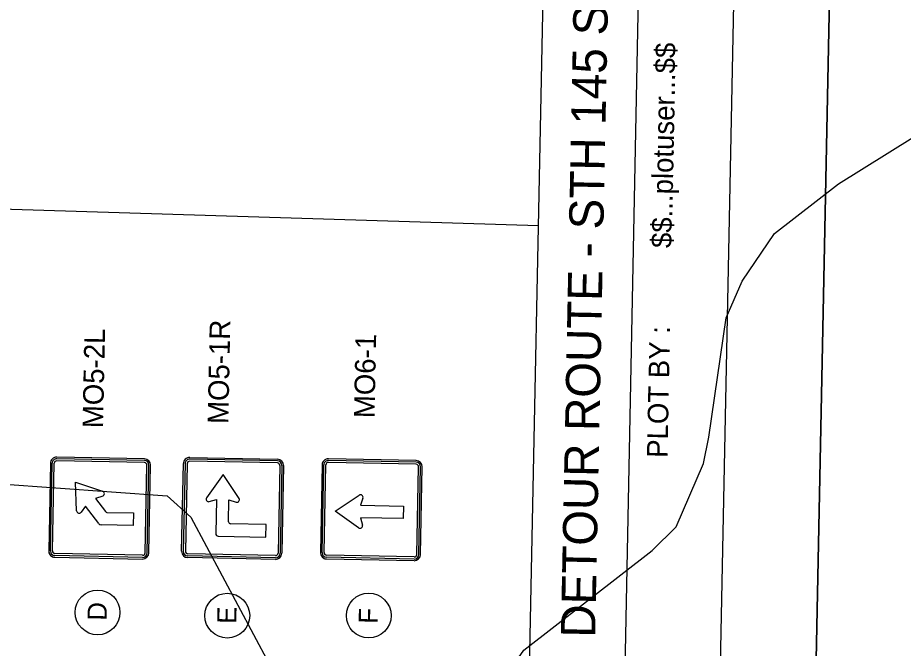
# Model space of a CAD drawing. Extents: x 331323 to 388339, y 121519 to 205315.
# Drawn here: x 365701 to 368485, y 141380 to 143362 of the extents above; entities that cross this region are included whole.
import ezdxf

# ---------------------------------------------------------------- set-up
doc = ezdxf.new("R2010")
doc.units = 0
for name, color, linetype in [('CA-TEXT', 7, 'Continuous'), ('Level 4', 7, 'Continuous'), ('Level 57', 7, 'Continuous'), ('P_RDWY_Text', 7, 'Continuous'), ('P_SGN_Cell', 7, 'Continuous'), ('PLT_Sheet_Border', 7, 'Continuous'), ('PLT_Sheet_Info', 7, 'Continuous')]:
    doc.layers.add(name, color=color, linetype=linetype)

msp = doc.modelspace()

# ---------------------------------------------------------------- linework, layer by layer
at = {"layer": 'CA-TEXT'}
for centre in [(365952.4, 141492.8), (366360.2, 141482.7), (366804.9, 141482.9)]:
    msp.add_circle(centre, 70.4, dxfattribs=at)
at = {"layer": 'Level 4'}
msp.add_lwpolyline([(367338.6, 142707.9), (362672.8, 142853), (355637.9, 142792.5)], dxfattribs=at)
at = {"layer": 'Level 57'}
for points in [[(367014.6, 141051.6), (367166.1, 141191.9), (367292.8, 141374.1), (367696, 141687.1), (367771.8, 141761.4), (367857, 141960.7), (367874.5, 142043.8), (367928, 142418.4), (367979.1, 142534.6), (368080.5, 142683.7), (368282.1, 142840.2), (368676.4, 143086.6), (369005.2, 143475.3), (369619.6, 144078.1), (370015, 144449.5), (370611, 144869.2), (370778.7, 144967.6), (370812.1, 144967.3)], [(364906.3, 142137.4), (365005.8, 142069.8), (365546.9, 141964.9), (365646.4, 141897.3), (366171.4, 141859.3), (366245.9, 141791.9), (366491.8, 141331.3), (366656.8, 141138.2), (366848, 141069.8), (367014.6, 141051.6)]]:
    msp.add_lwpolyline(points, dxfattribs=at)
at = {"layer": 'P_RDWY_Text'}
msp.add_lwpolyline([(354790.8, 130527.7), (355201.6, 150923.5), (368398.9, 150657.7), (367988.1, 130261.9)], close=True, dxfattribs=at)
at = {"layer": 'P_SGN_Cell'}
for p, q in [((366099.9, 141970.3), (365824.3, 141975.8)), ((366100, 141975.5), (365824.4, 141981.1)), ((366517.7, 141969.1), (366242.2, 141974.7)), ((366242.3, 141979.9), (366517.8, 141974.4)), ((366954, 141970.4), (366678.4, 141975.9)), ((365804.4, 141961.8), (365798.8, 141686.2)), ((365804.1, 141686.1), (365809.6, 141961.7)), ((365810.6, 141686), (365816.2, 141961.5)), ((366099.8, 141963.7), (365824.2, 141969.3)), ((366101.9, 141680.1), (366107.5, 141955.7)), ((366108.5, 141680), (366114, 141955.5)), ((366113.7, 141679.9), (366119.3, 141955.4)), ((366216.6, 141685.1), (366222.2, 141960.6)), ((366227.4, 141960.5), (366221.9, 141685)), ((366234, 141960.4), (366228.5, 141684.8)), ((366517.6, 141962.6), (366242, 141968.1)), ((366525.3, 141954.5), (366519.8, 141679)), ((366531.9, 141954.4), (366526.3, 141678.8)), ((366537.1, 141954.3), (366531.6, 141678.7)), ((366658.4, 141956.6), (366652.8, 141681.1)), ((366658.1, 141681), (366663.6, 141956.5)), ((366664.6, 141680.8), (366670.2, 141956.4)), ((366953.8, 141958.6), (366678.2, 141964.1)), ((366953.9, 141965.1), (366678.3, 141970.7)), ((366955.9, 141675), (366961.5, 141950.5)), ((366962.5, 141674.8), (366968, 141950.4)), ((366967.7, 141674.7), (366973.3, 141950.3)), ((366347.5, 141926.6), (366294.9, 141853.4)), ((366397.1, 141851.3), (366347.5, 141926.6)), ((365886.6, 141812.3), (365883, 141902.4)), ((365883, 141902.4), (365968.4, 141873.6)), ((365968.6, 141858.7), (365946.4, 141850.6)), ((365946.4, 141850.6), (365977, 141809.8)), ((366303.5, 141841.2), (366326.3, 141847.6)), ((366326.3, 141847.6), (366324.1, 141740.7)), ((366364.2, 141777.9), (366365.6, 141846.8)), ((366365.6, 141846.8), (366388.1, 141839.5)), ((366699.6, 141811.6), (366774.9, 141861.2)), ((366786.8, 141852.2), (366779.5, 141829.6)), ((365914.9, 141827), (365900.8, 141807.9)), ((365956.2, 141771.8), (365914.9, 141827)), ((365982.1, 141807.2), (366065.1, 141805.5)), ((366772.9, 141759), (366699.6, 141811.6)), ((366779.5, 141829.6), (366913.9, 141826.9)), ((366913.9, 141826.9), (366913.1, 141787.6)), ((366065.1, 141805.5), (366064.3, 141766.1)), ((366913.1, 141787.6), (366778.7, 141790.3)), ((366778.7, 141790.3), (366785.1, 141767.5)), ((366064.3, 141766.1), (365963.4, 141768.2)), ((366482.2, 141769), (366370.7, 141771.2)), ((366481.4, 141729.6), (366482.2, 141769)), ((366331.8, 141732.6), (366481.4, 141729.6)), ((366093.8, 141665.8), (365818.2, 141671.4)), ((366093.9, 141672.4), (365818.3, 141677.9)), ((366511.6, 141664.7), (366236, 141670.2)), ((366511.7, 141671.2), (366236.2, 141676.8)), ((366947.9, 141667.3), (366672.3, 141672.8)), ((365818.1, 141666.1), (366093.7, 141660.6)), ((366511.5, 141659.4), (366235.9, 141665)), ((366672.1, 141661), (366947.7, 141655.5)), ((366947.8, 141660.7), (366672.2, 141666.2))]:
    msp.add_line(p, q, dxfattribs=at)
for centre, radius, start, end in [((365824, 141961.4), 19.7, 88.8462, 178.8462), ((365824, 141961.4), 14.4, 88.8462, 178.8462), ((366099.6, 141955.8), 19.7, 358.8462, 88.8462), ((366241.9, 141960.2), 19.7, 88.8462, 178.8462), ((366241.9, 141960.2), 14.4, 88.8462, 178.8462), ((366517.5, 141954.7), 19.7, 358.8462, 88.8462), ((366678, 141956.3), 19.7, 88.8468, 178.8468), ((365824, 141961.4), 7.88, 88.8462, 178.8462), ((366099.6, 141955.8), 7.88, 358.8462, 88.8462), ((366099.6, 141955.8), 14.4, 358.8462, 88.8462), ((366241.9, 141960.2), 7.88, 88.8462, 178.8462), ((366517.5, 141954.7), 7.88, 358.8462, 88.8462), ((366517.5, 141954.7), 14.4, 358.8462, 88.8462), ((366678, 141956.3), 14.4, 88.8468, 178.8468), ((366678, 141956.3), 7.87, 88.8468, 178.8468), ((366953.6, 141950.7), 7.87, 358.8468, 88.8468), ((366953.6, 141950.7), 14.4, 358.8468, 88.8468), ((366953.6, 141950.7), 19.7, 358.8468, 88.8468), ((365965.9, 141866.1), 7.87, 290.0436, 71.3759), ((366779.3, 141854.6), 7.87, 342.043, 123.3753), ((366301.3, 141848.8), 7.87, 144.3166, 285.6488), ((366390.6, 141847), 7.87, 252.0436, 33.3759), ((365894.5, 141812.6), 7.87, 182.3166, 323.6488), ((365982.2, 141813.7), 6.56, 216.8461, 268.8462), ((365963.6, 141777.3), 9.19, 216.8459, 268.8462), ((366370.8, 141777.8), 6.56, 178.8462, 268.8462), ((366777.5, 141765.4), 7.87, 234.316, 15.6482), ((366332, 141740.5), 7.88, 178.8462, 268.8462), ((365818.5, 141685.8), 19.7, 178.8462, 268.8462), ((365818.5, 141685.8), 19.7, 178.8462, 213.1868), ((365818.5, 141685.8), 14.4, 178.8462, 268.8462), ((365818.5, 141685.8), 19.7, 244.1347, 268.8462), ((365818.5, 141685.8), 7.88, 178.8462, 268.8462), ((366094.1, 141680.3), 19.7, 268.8462, 358.8462), ((366094.1, 141680.3), 14.4, 268.8462, 358.8462), ((366094.1, 141680.3), 7.88, 268.8462, 358.8462), ((366236.3, 141684.7), 19.7, 178.8462, 268.8462), ((366236.3, 141684.7), 14.4, 178.8462, 268.8462), ((366236.3, 141684.7), 7.88, 178.8462, 268.8462), ((366511.9, 141679.1), 19.7, 268.8462, 358.8462), ((366511.9, 141679.1), 14.4, 268.8462, 358.8462), ((366511.9, 141679.1), 7.88, 268.8462, 358.8462), ((366672.5, 141680.7), 19.7, 178.8468, 268.8468), ((366672.5, 141680.7), 14.4, 178.8468, 268.8468), ((366672.5, 141680.7), 7.87, 178.8468, 268.8468), ((366948.1, 141675.1), 19.7, 268.8468, 358.8468), ((366948.1, 141675.1), 14.4, 268.8468, 358.8468), ((366948.1, 141675.1), 7.87, 268.8468, 358.8468), ((366672.5, 141680.7), 19.7, 239.4503, 268.8468)]:
    msp.add_arc(centre, radius, start, end, dxfattribs=at)
at = {"layer": 'PLT_Sheet_Border'}
for points in [[(367988.1, 130261.9), (368398.9, 150657.7), (355201.6, 150923.5), (354790.8, 130527.7)], [(367691.1, 130411.9), (368091, 150267.9), (355493.5, 150521.6), (355093.6, 130665.6)]]:
    msp.add_lwpolyline(points, close=True, dxfattribs=at)
at = {"layer": 'PLT_Sheet_Info'}
for p, q in [((367103.6, 131038.8), (367484.2, 149935)), ((367403.5, 131032.8), (367784.1, 149929))]:
    msp.add_line(p, q, dxfattribs=at)

# ---------------------------------------------------------------- texts
at = {"layer": 'CA-TEXT'}
for s, p in [('D', (365980.7, 141466.7)), ('E', (366388.4, 141456.6)), ('F', (366833.1, 141456.8))]:
    msp.add_text(s, height=60, rotation=88.8468, dxfattribs=at).set_placement(p)
at = {"layer": 'P_SGN_Cell'}
for s, rotation, p in [('MO5-1R', 88.8462, (366363.4, 142084.8)), ('MO5-2L', 88.8462, (365969.8, 142071.5)), ('MO6-1', 88.8468, (366823.1, 142103))]:
    msp.add_text(s, height=64.8, rotation=rotation, dxfattribs=at).set_placement(p)
at = {"layer": 'PLT_Sheet_Info'}
for s, height, p in [('DETOUR ROUTE - STH 145 SB OFF RAMP                   ', 108, (367516.6, 141412.6)), ('$$...plotuser...$$', 64.8, (367757.3, 142638)), ('PLOT BY :', 64.8, (367744, 141978.2))]:
    msp.add_text(s, height=height, rotation=88.8462, dxfattribs=at).set_placement(p)

doc.saveas('drawing.dxf')
